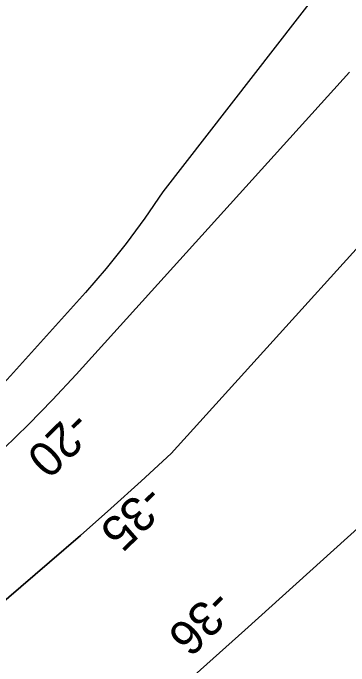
# Model space of a CAD drawing. Extents: x 3923531 to 3943530, y 207391 to 229799.
# Drawn here: x 3930673 to 3930996, y 213804 to 214433 of the extents above; entities that cross this region are included whole.
import ezdxf

# ---------------------------------------------------------------- set-up
doc = ezdxf.new("R2010")
doc.units = 0
for name, color, linetype in [('V-RIVR-RANG', 7, 'Continuous'), ('V-TOPO-DPTH', 7, 'Continuous'), ('V-TOPO-MINR', 7, 'Continuous')]:
    doc.layers.add(name, color=color, linetype=linetype)

msp = doc.modelspace()

# ---------------------------------------------------------------- linework, layer by layer
at = {"layer": 'V-TOPO-DPTH'}
for points in [[(3930083.42, 213409.58), (3930101.58, 213423.44), (3930119.97, 213437.02), (3930138.39, 213450.55), (3930156.86, 213464.01), (3930175.36, 213477.42), (3930268.66, 213544.79), (3930333.21, 213592.66), (3930396.91, 213641.59), (3930459.36, 213692.13), (3930520.96, 213743.73), (3930707.8, 213904.31), (3930737.43, 213930.07), (3930766.87, 213956.05), (3930796.02, 213982.36), (3930824.98, 214008.89), (3931395.67, 214639.33)], [(3930083.42, 213409.58), (3930101.58, 213423.44), (3930119.97, 213437.02), (3930138.39, 213450.55), (3930156.86, 213464.01), (3930175.36, 213477.42), (3930268.66, 213544.79), (3930333.21, 213592.66), (3930396.91, 213641.59), (3930459.36, 213692.13), (3930520.96, 213743.73), (3930707.8, 213904.31), (3930737.43, 213930.07), (3930766.87, 213956.05), (3930796.02, 213982.36), (3930824.98, 214008.89), (3931395.67, 214639.33)], [(3930996.63, 214375.9), (3930733.34, 214084.71), (3930710.68, 214060.43), (3930687.52, 214036.67), (3930663.6, 214013.65), (3930639.19, 213991.14), (3930515.4, 213880.63), (3930428.72, 213803.24), (3930342.04, 213725.84), (3930255.37, 213648.43), (3930168.71, 213571.02), (3929986.55, 213408.3), (3929957.01, 213381.85), (3929927.52, 213355.35), (3929898.09, 213328.78), (3929868.7, 213302.16), (3929857.71, 213292.18), (3929822.64, 213260.78), (3929787.28, 213229.73), (3929751.47, 213199.19), (3929715.37, 213168.98), (3929345.89, 212722.35)], [(3931255.16, 214162.68), (3930895.8, 213838.74), (3930883.64, 213827.81), (3930871.46, 213816.9), (3930859.26, 213806.03), (3930847.03, 213795.17), (3930725.04, 213687.12), (3930652.66, 213621.37), (3930581.4, 213554.45), (3930511.84, 213485.77), (3930443.41, 213415.91), (3930143.79, 213102.34)], [(3930143.79, 213102.34), (3930443.41, 213415.91), (3930511.84, 213485.77), (3930581.4, 213554.45), (3930652.66, 213621.37), (3930725.04, 213687.12), (3930847.03, 213795.17), (3930859.26, 213806.03), (3930871.46, 213816.9), (3930883.64, 213827.81), (3930895.8, 213838.74), (3931255.16, 214162.68)]]:
    msp.add_lwpolyline(points, dxfattribs=at)
at = {"layer": 'V-TOPO-MINR'}
for points in [[(3931247.3, 214814.92), (3930817, 214260.62), (3930799.58, 214235.42), (3930781.44, 214210.79), (3930762.21, 214187), (3930742.25, 214163.76), (3930670.06, 214083.42), (3930663.15, 214075.95), (3930656.09, 214068.61), (3930648.83, 214061.49), (3930641.42, 214054.51), (3930598.91, 214015.59), (3930570.01, 213989.4), (3930540.94, 213963.4), (3930511.63, 213937.68), (3930482.14, 213912.15), (3930437, 213873.46)], [(3931395.67, 214639.33), (3930824.98, 214008.89), (3930796.02, 213982.36), (3930766.87, 213956.05), (3930737.43, 213930.07), (3930707.8, 213904.31), (3930520.96, 213743.73), (3930459.36, 213692.13), (3930396.91, 213641.59), (3930333.21, 213592.66), (3930268.66, 213544.79), (3930175.36, 213477.42), (3930156.86, 213464.01), (3930138.39, 213450.55), (3930119.97, 213437.02), (3930101.58, 213423.44), (3930083.42, 213409.58)], [(3930996.63, 214375.9), (3930733.34, 214084.71), (3930710.68, 214060.43), (3930687.52, 214036.67), (3930663.6, 214013.65), (3930639.19, 213991.14), (3930515.4, 213880.63), (3930428.72, 213803.24), (3930342.04, 213725.84), (3930255.37, 213648.43), (3930168.71, 213571.02), (3929986.55, 213408.3), (3929957.01, 213381.85), (3929927.52, 213355.35), (3929898.09, 213328.78), (3929868.7, 213302.16), (3929857.71, 213292.18), (3929822.64, 213260.78), (3929787.28, 213229.73), (3929751.47, 213199.19), (3929715.37, 213168.98)], [(3931255.16, 214162.68), (3930895.8, 213838.74), (3930883.64, 213827.81), (3930871.46, 213816.9), (3930859.26, 213806.03), (3930847.03, 213795.17), (3930725.04, 213687.12), (3930652.66, 213621.37), (3930581.4, 213554.45), (3930511.84, 213485.77), (3930443.41, 213415.91), (3930143.79, 213102.34)]]:
    msp.add_lwpolyline(points, dxfattribs=at)

# ---------------------------------------------------------------- texts
at = {"layer": 'V-RIVR-RANG'}
for s, rotation, p in [('-20', 224.38833, (3930729.97, 214052.26)), ('-35', 224.38833, (3930800.57, 213981.42)), ('-36', 224.527, (3930866.05, 213880.83))]:
    msp.add_text(s, height=33.5, rotation=rotation, dxfattribs=at).set_placement(p)

doc.saveas('drawing.dxf')
